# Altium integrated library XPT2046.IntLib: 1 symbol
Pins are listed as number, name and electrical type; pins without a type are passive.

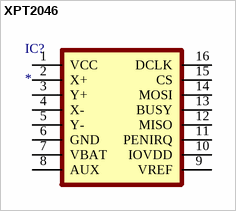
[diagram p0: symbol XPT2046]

## XPT2046
designator IC?
RASPBERRY PI 3.5 TFT DISPLAY; MF: Xptek; MP: XPT2046
footprint TSSOP16
pins: 1 VCC, 2 X+, 3 Y+, 4 X-, 5 Y-, 6 GND, 7 VBAT, 8 AUX, 9 VREF, 10 IOVDD, 11 PENIRQ, 12 MISO, 13 BUSY, 14 MOSI, 15 CS, 16 DCLK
